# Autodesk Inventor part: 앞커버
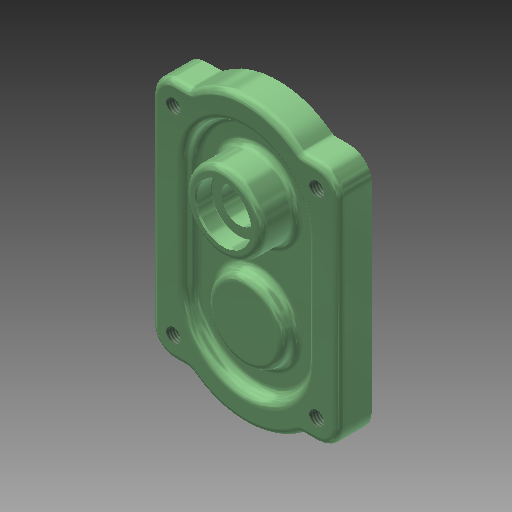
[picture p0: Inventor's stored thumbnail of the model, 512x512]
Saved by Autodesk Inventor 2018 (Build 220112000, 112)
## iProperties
Created: 2013-07
Part Number: 앞커버
Document SubType Name: Modeling
Designer: 한국산업디자인학원
Density: 1 g/cm^3
Mass: 127.306 g
Surface Area: 321.226 cm^2
Volume: 127.306 cm^3
Material: 알루미늄 6061
Appearance: 알루미늄 - 평지(1)
Author: 한국산업디자인학원
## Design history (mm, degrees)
sketch "스케치1"
  geometry: L1 (-28.5, -82.106)-(-28.5, -34.106) reference; L2 (28.5, -34.106)-(28.5, -82.106) reference; L3 (-42.5, -103.106)-(-42.5, -13.106) reference; L4 (-26.325, -113.106)-(-32.5, -113.106) reference; L5 (32.5, -113.106)-(26.325, -113.106) reference; L6 (42.5, -13.106)-(42.5, -103.106) reference; L7 (26.325, -3.106)-(32.5, -3.106) reference; L8 (-32.5, -3.106)-(-26.325, -3.106) reference; C1 r 4.5 at (-32.5, -13.106) reference; C2 r 4.5 at (32.5, -103.106) reference; C3 r 4.5 at (-32.5, -103.106) reference; C4 r 4.5 at (32.5, -13.106) reference; A1 r 28.5 centre (0, -82.106) between (-28.5, -82.106) and (28.5, -82.106) reference; A2 r 28.5 centre (0, -34.106) between (28.5, -34.106) and (-28.5, -34.106) reference; A3 r 10 centre (-32.5, -103.106) between (-42.5, -103.106) and (-32.5, -113.106) reference; A4 r 3 centre (-26.325, -116.106) between (-24.488, -113.734) and (-26.325, -113.106) reference; A5 r 40 centre (0, -82.106) between (-24.488, -113.734) and (24.488, -113.734) reference; A6 r 3 centre (26.325, -116.106) between (26.325, -113.106) and (24.488, -113.734) reference; A7 r 10 centre (32.5, -103.106) between (32.5, -113.106) and (42.5, -103.106) reference; A8 r 10 centre (32.5, -13.106) between (42.5, -13.106) and (32.5, -3.106) reference; A9 r 3 centre (26.325, -0.106) between (24.488, -2.478) and (26.325, -3.106) reference; A10 r 40 centre (0, -34.106) between (24.488, -2.478) and (-24.488, -2.478) reference; A11 r 3 centre (-26.325, -0.106) between (-26.325, -3.106) and (-24.488, -2.478) reference; A12 r 10 centre (-32.5, -13.106) between (-32.5, -3.106) and (-42.5, -13.106) reference
extrude "돌출1" new body sketch "스케치1" distance "d0" = 15; taper "d1" = 0 deg
sketch "스케치2"
  geometry: L1 (-28.5, -34.106)-(-28.5, -82.106) reference; L2 (28.5, -82.106)-(28.5, -34.106) reference; A1 r 28.5 centre (0, -34.106) between (28.5, -34.106) and (-28.5, -34.106) reference; A2 r 28.5 centre (0, -82.106) between (-28.5, -82.106) and (28.5, -82.106) reference
extrude "돌출2" join sketch "스케치2" distance "d2" = 5; taper "d3" = 0 deg
sketch "스케치11"
  geometry: L1 (-103.106, 15)-(-13.106, 15) reference; L2 (-82.106, -5)-(-110.606, -5) reference; L3 (-82.106, -5)-(-82.106, 15); L4 (-96.106, -5)-(-96.106, 8); L5 (-96.106, 8)-(-92.106, 8); L6 (-90.106, 10)-(-82.106, 10); A1 r 2 centre (-90.106, 8) between (-90.106, 10) and (-92.106, 8); 1 further point
  constraints: 8 end point, 4 point on line, 2 parallel, 2 perpendicular, 2 point on circle, 1 centre point, 1 tangent, 1 vertical alignment
  dimensions: "d77" = 13 distance of L4.start L4.end; "d78" = 2 distance between parallel lines of L6 L5; "d79" = 28 diameter of L4 L3; "d80" = 20 diameter of L5.end L3
revolve "회전1" sketch "스케치11" stored, may be unused: angle "d81" = 90 deg
sketch "스케치8"
  geometry: L1 (28, -82.106)-(28, -34.106); L2 (-28, -82.106)-(-28, -34.106); C1 r 17.5 at (0, -82.106); C2 r 17.5 at (0, -34.106); A1 r 28 centre (0, -82.106) between (28, -82.106) and (-28, -82.106); A2 r 28 centre (0, -34.106) between (-17.161, -56.231) and (17.161, -56.231); A3 r 40 centre (0, -34.106) between (24.488, -2.478) and (-24.488, -2.478) reference; A4 r 40 centre (0, -82.106) between (-24.488, -113.734) and (24.488, -113.734) reference
  constraints: 6 point on circle, 4 centre point, 4 end point, 3 concentric, 2 equal radius, 2 parallel, 1 coincident, 1 tangent, 1 vertical
  dimensions: "d43" = 56 diameter of A1; "d44" = 35 diameter of C1
extrude "돌출5" cut sketch "스케치8" distance "d47" = 6; taper "d48" = 0 deg
sketch "스케치12"
  geometry: C1 r 17.5 at (0, 0) reference; 1 further point
extrude "돌출7" join sketch "스케치12" distance "d87" = 10; taper "d88" = 0 deg
fillet "모깎기1" dims "d49" = 3
fillet "모깎기2" dims "d50" = 3, "d51" = 0.3
chamfer "모따기1" distance "d52" = 1; stored, may be unused: second distance "d53" = 2, angle "d54" = 45 deg
sketch "스케치13"
  geometry: L1 (-5.606, -5)-(-34.106, -5) reference; L2 (-48.606, 25)-(-19.606, 25) reference; L3 (-34.106, -5)-(-34.106, 25); L4 (-20.106, -5)-(-20.106, 8); L5 (-20.106, 8)-(-26.035, 8); L6 (-26.035, 8)-(-26.035, 17.7); L7 (-26.035, 17.7)-(-21.906, 17.7); L8 (-21.606, 18)-(-21.606, 25); L9 (-96.106, 8)-(-68.106, 8) reference; A1 r 0.3 centre (-21.906, 18) between (-21.906, 17.7) and (-21.606, 18); 3 further points
  constraints: 12 end point, 4 point on line, 3 parallel, 2 perpendicular, 2 point on circle, 2 tangent, 1 centre point, 1 collinear, 1 midpoint, 1 other
  dimensions: "d89" = 28 distance of L9.end L9.start (derived); "d90" = 28 diameter of L4 L3 (= d89); "d91" = 1 distance from line of L6 point (-27.035, 59); "d93" = 7.3 distance between parallel lines of L7 L2; "d94" = 25 diameter of L8 L3; "d98" = 0.3 radius of A1
revolve "회전2" sketch "스케치13" stored, may be unused: angle "d92" = 90 deg
chamfer "모따기2" distance "d95" = 0.7; stored, may be unused: second distance "d96" = 2, angle "d97" = 30 deg
sketch "스케치14"
  geometry: C1 r 4.5 at (-32.5, -13.106) reference; C2 r 4.5 at (32.5, -13.106) reference; C3 r 4.5 at (32.5, -103.106) reference; C4 r 4.5 at (-32.5, -103.106) reference; 1 further point
hole "구멍7" sketch "스케치14" at (-32.5, -13.106), (32.5, -13.106), (32.5, -103.106), (-32.5, -103.106) diameter "d99" = 6.647; stored, may be unused: countersink angle "d103" = 90 deg, drill point angle "d105" = 118 deg; dims "d100" = 20, "d101" = 4, "d102" = 2, "d104" = 8
node "솔리드1"
node "참조10"
node "참조11"
node "참조12"
node "참조13"
node "참조14"
node "참조19"
node "참조20"
node "참조21"
node "참조22"
